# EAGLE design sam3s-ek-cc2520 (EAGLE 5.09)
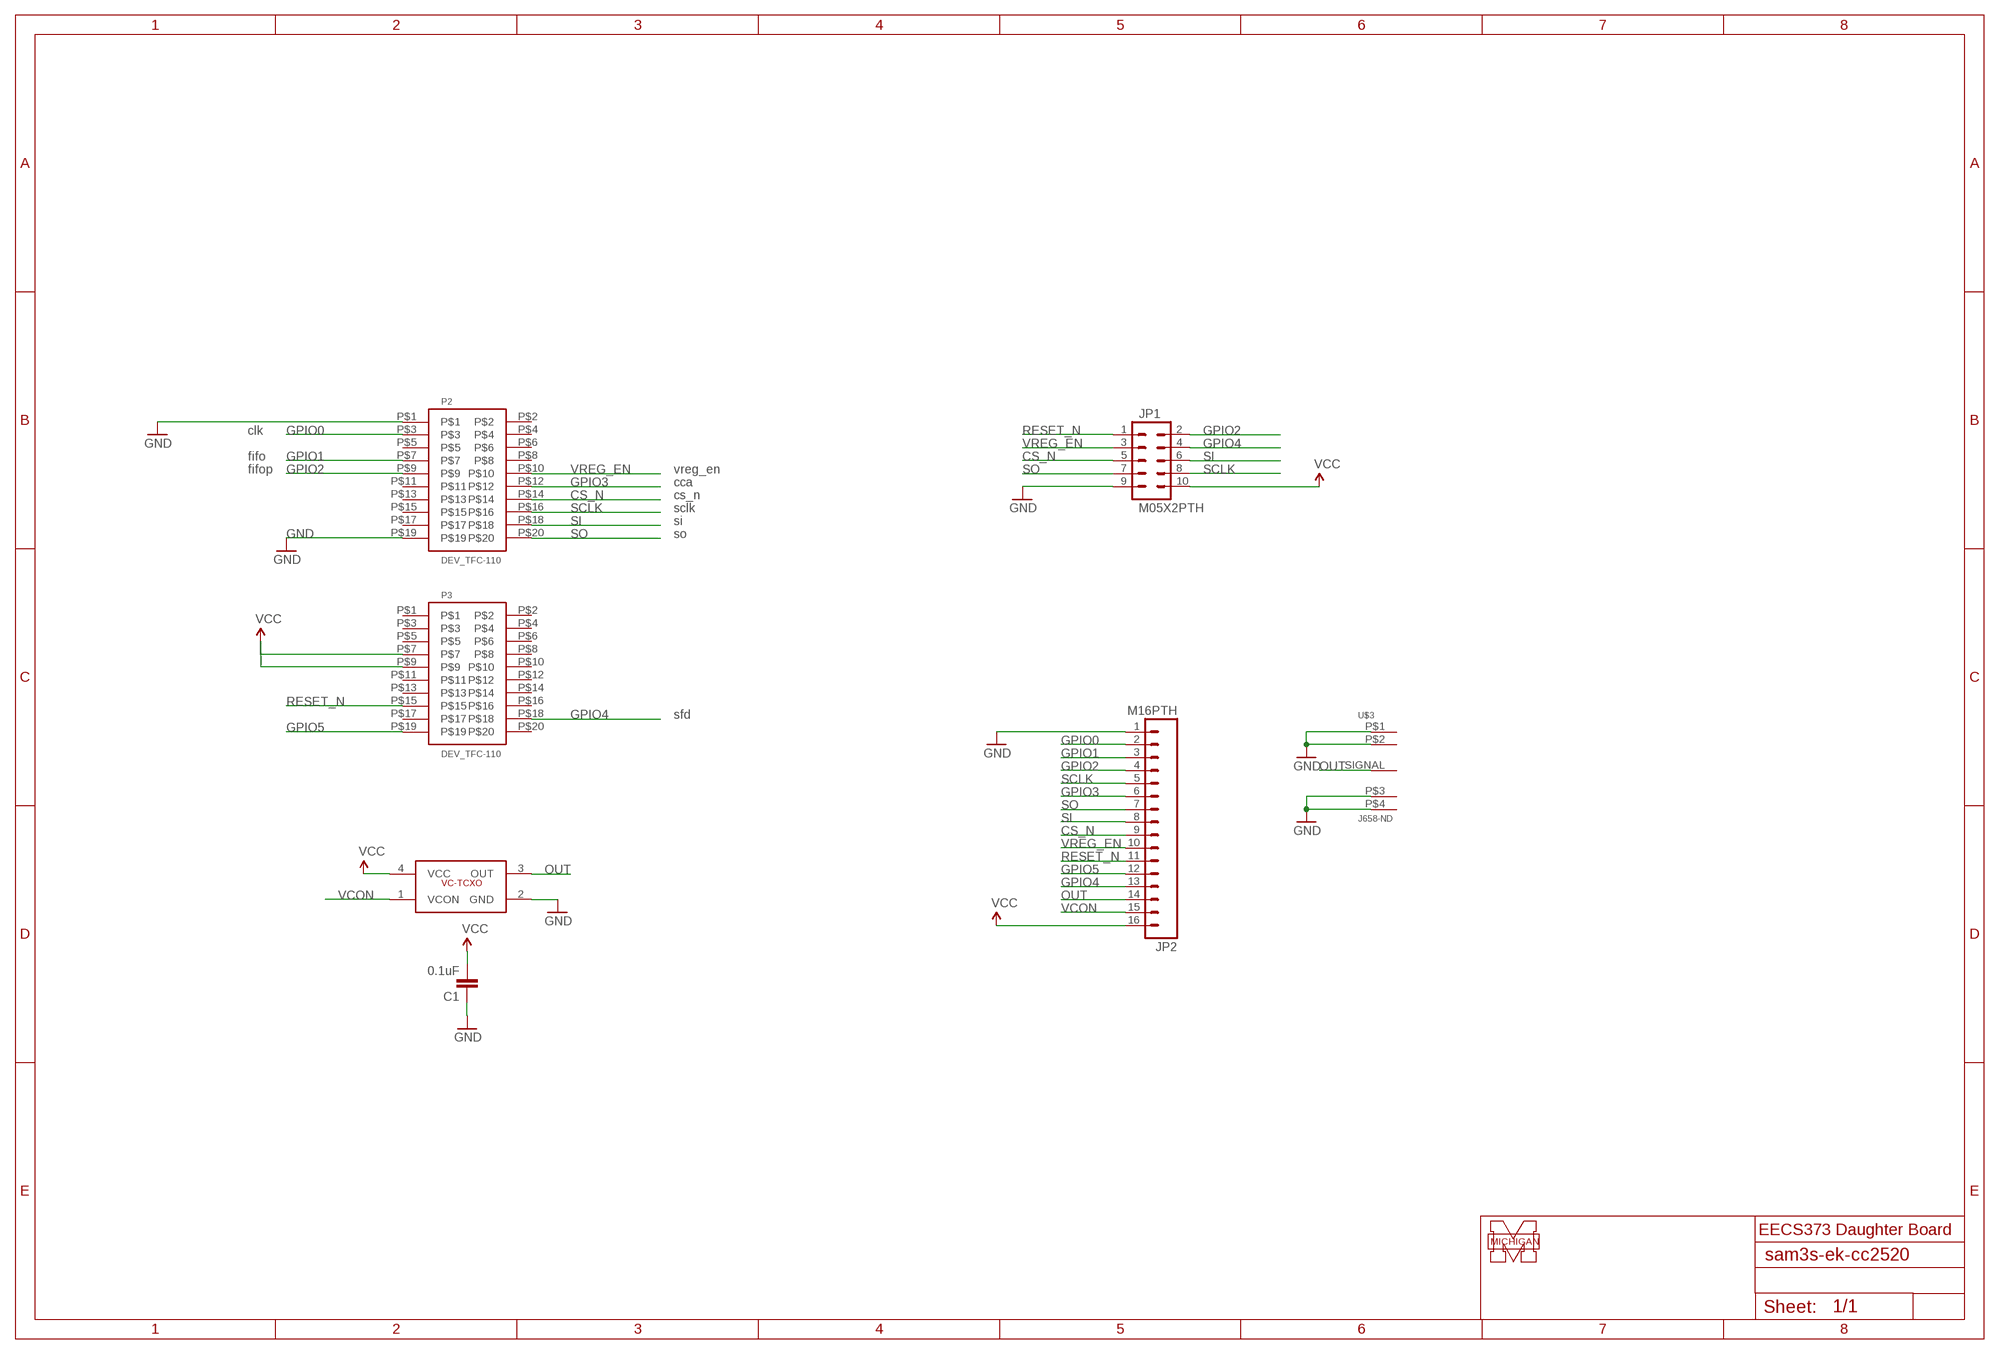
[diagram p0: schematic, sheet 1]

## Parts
C1  0.1uF  CAP0603-CAP  [0603-CAP]
JP1  M05X2PTH  [AVR_ICSP]
JP2  M16PTH  [1X16]
P2  DEV_TFC-110  [TFC-110]
P3  DEV_TFC-110  [TFC-110]
U$2  KT3225  [KT3225]
U$3  J658-ND  [SMA-SMD]

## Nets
CS_N: JP1.5 JP2.9 P2.P$14
GND: C1.1 JP1.9 JP2.1 P2.P$1 P2.P$19 U$2.2(GND) U$3.P$1(GND1) U$3.P$2(GND2) U$3.P$3(GND3) U$3.P$4(GND4)
GPIO0: JP2.2 P2.P$3
GPIO1: JP2.3 P2.P$7
GPIO2: JP1.2 JP2.4 P2.P$9
GPIO3: JP2.6 P2.P$12
GPIO4: JP1.4 JP2.13 P3.P$18
GPIO5: JP2.12 P3.P$19
OUT: JP2.14 U$2.3(OUT) U$3.SIGNAL
RESET_N: JP1.1 JP2.11 P3.P$15
SCLK: JP1.8 JP2.5 P2.P$16
SI: JP1.6 JP2.8 P2.P$18
SO: JP1.7 JP2.7 P2.P$20
VCC: C1.2 JP1.10 JP2.16 P3.P$7 P3.P$9 U$2.4(VCC)
VCON: JP2.15 U$2.1(VCON)
VREG_EN: JP1.3 JP2.10 P2.P$10
Unconnected: P2.P$2 P2.P$4 P2.P$5 P2.P$6 P2.P$8 P2.P$11 P2.P$13 P2.P$15 P2.P$17 P3.P$1 P3.P$2 P3.P$3 P3.P$4 P3.P$5 P3.P$6 P3.P$8 P3.P$10 P3.P$11 P3.P$12 P3.P$13 P3.P$14 P3.P$16 P3.P$17 P3.P$20

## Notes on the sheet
- clk
- fifo
- fifop | vreg_en
- cca
- cs_n
- sclk
- si
- so
- sfd
- EECS373 Daughter Board
- MICHIGAN

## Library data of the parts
C1 = SparkFun:CAP: Capacitor
JP1 = SparkFun:M05X2: Header 5x2 Standard 10-pin dual row 0.1" header. Commonly used with AVR-ISP. Use with Spark Fun Electronics SKU: PRT-00778
JP2 = SparkFun:M16
P2 P3 = EECS370:DEV_TFC-110
U$2 = utah:KT3225
U$3 = sam:J658-ND

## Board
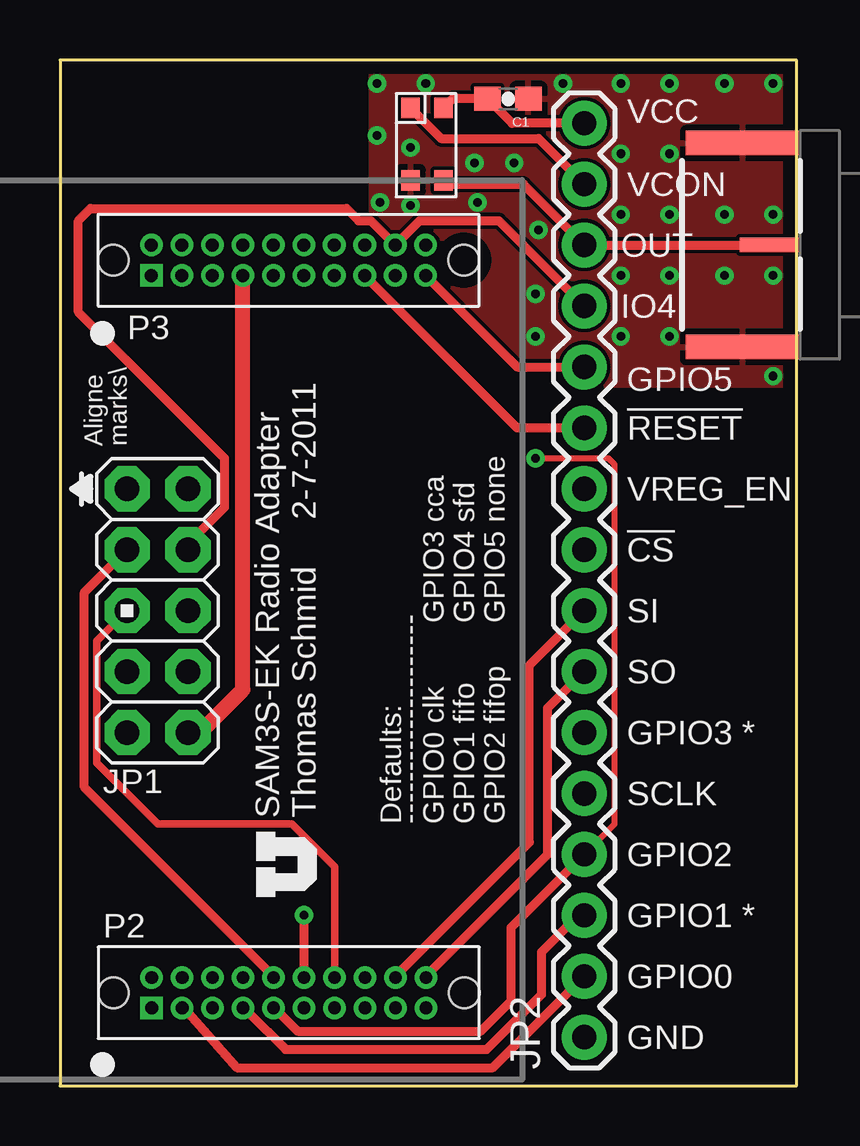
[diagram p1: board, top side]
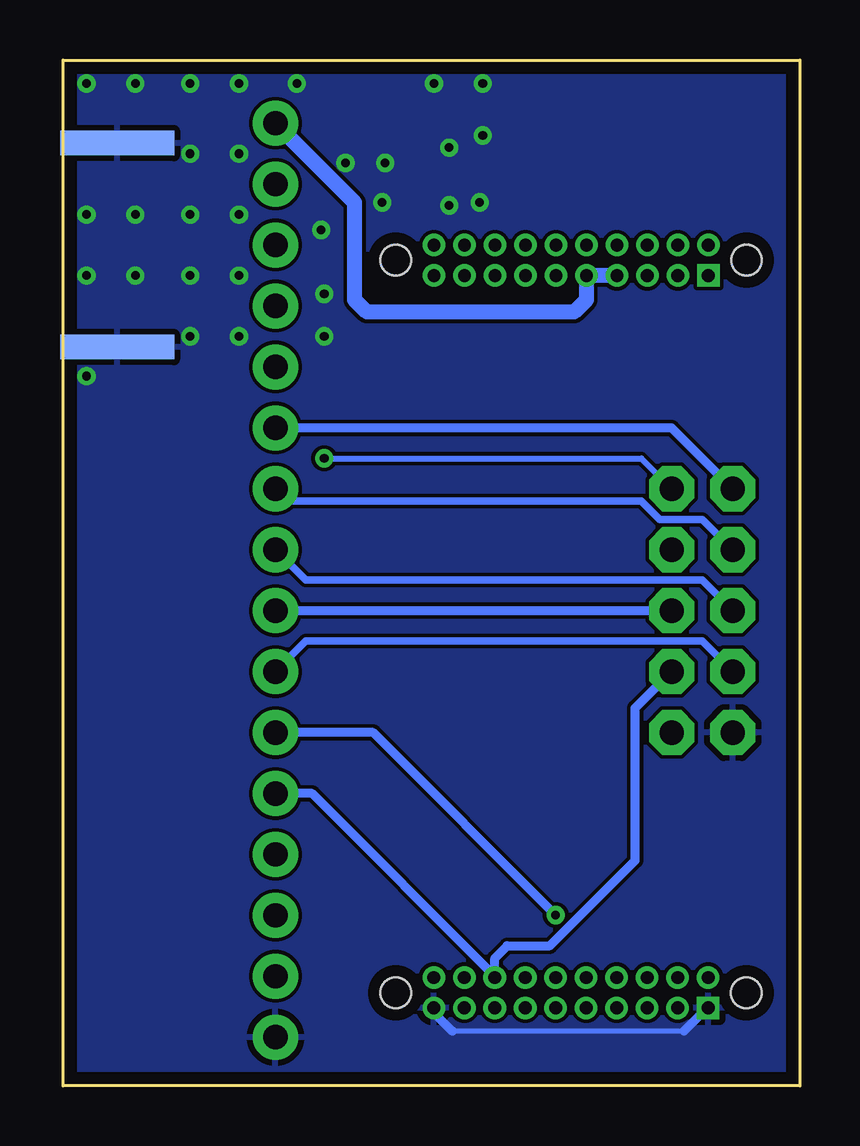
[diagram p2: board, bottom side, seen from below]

Size 30.69 x 42.77 mm. Coordinates in mm from the lower left corner, seen from the top.
Outline: 0,0 30.69,0 30.69,42.77 0,42.77 0,0
Copper layers (1*16): Top 0.0178mm / dielectric 1.4986mm / Bottom 0.0178mm
Design rules "SSC-EAGLE-2Lyr_v1.0.0.3 *": minimum track width 8mil, minimum drill 14mil, track to track 6mil, track to pad 6mil, pad to pad 6mil, via to via 6mil, smd to smd 6mil, copper to edge 20mil, drill to drill 16mil, minimum pad ring 8mil, minimum via ring 8mil, stop-mask expansion 3mil, vias tented up to drill 14mil, thermal gap 10mil

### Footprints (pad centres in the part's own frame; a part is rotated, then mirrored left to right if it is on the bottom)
0603-CAP = smd 1.1 x 1: 1 -0.85,0; 2 0.85,0
AVR_ICSP = drill 1.016 pad 1.88 octagon: 1 -1.27,5.08; 2 1.27,5.08; 3 -1.27,2.54; 4 1.27,2.54; 5 -1.27,0; 6 1.27,0; 7 -1.27,-2.54; 8 1.27,-2.54; 9 -1.27,-5.08; 10 1.27,-5.08
1X16 = drill 1.016 pad 1.88 round: 1 0,0; 2 2.54,0; 3 5.08,0; 4 7.62,0; 5 10.16,0; 6 12.7,0; 7 15.24,0; 8 17.78,0; 9 20.32,0; 10 22.86,0; 11 25.4,0; 12 27.94,0; 13 30.48,0; 14 33.02,0; 15 35.56,0; 16 38.1,0
TFC-110 = drill 0.533 square: P$1 -5.715,-0.635 | drill 0.533 round: P$2 -5.715,0.635; P$3 -4.445,-0.635; P$4 -4.445,0.635; P$5 -3.175,-0.635; P$6 -3.175,0.635; P$7 -1.905,-0.635; P$8 -1.905,0.635; P$9 -0.635,-0.635; P$10 -0.635,0.635; P$11 0.635,-0.635; P$12 0.635,0.635; P$13 1.905,-0.635; P$14 1.905,0.635; P$15 3.175,-0.635; P$16 3.175,0.635; P$17 4.445,-0.635; P$18 4.445,0.635; P$19 5.715,-0.635; P$20 5.715,0.635 | hole 1.27: 7.305,0; -7.305,0
KT3225 = smd 0.87 x 0.78: 1 0,0; 2 3.02,0; 3 3.02,1.37; 4 0,1.37
SMA-SMD = smd 1.02 x 4.75: P$1 -4.25,0; P$2 4.25,0 | smd 1.02 x 4.75 bottom: P$3 4.25,0; P$4 -4.25,0 | smd 0.6 x 2.5: SIGNAL 0,1.125

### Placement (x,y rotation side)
C1  18.67,41.15 180 top
JP1  4.06,19.81 0 top
JP2  21.84,2.03 90 top
P2  9.53,3.89 0 top
P3  9.52,34.42 0 top
U$1  [UTAH_LOGO]  10.67,7.87 90 top
U$2  14.61,40.77 270 top
U$3  28.45,35.05 270 top

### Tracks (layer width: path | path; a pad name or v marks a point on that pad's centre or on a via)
CS_N
  Top 0.305: JP1.5 1.52,18.54 1.52,13.46 4.06,10.92 9.65,10.92 11.44,9.14 P2.P$14
  Bottom 0.203: P2.P$14 11.43,4.57
  Bottom 0.305: JP1.5 4.06,21.08 20.57,21.08 JP2.9
GND  (via drill 0.36)
  Bottom 0.203: 4.83,2.29 14.48,2.29 | 4.06,3.05 P2.P$1
  Bottom 0.254: 15.24,3.05 P2.P$19
  Bottom 0.381: 4.83,2.29 4.06,3.05 | 14.48,2.29 15.24,3.05
  other vias: 13.33,36.83 14.61,36.7 17.4,36.83 19.94,35.69 18.92,38.48 17.27,38.48 14.61,39.12 13.21,39.62 13.21,41.78 15.24,41.78 20.96,41.78 23.37,41.78 25.4,41.78 25.4,38.86 23.37,38.86 23.37,36.32 25.4,36.32 23.37,33.78 25.4,33.78 27.69,33.78 29.72,33.78 29.72,36.32 27.69,36.32 27.69,41.78 29.72,41.78 29.72,29.59 25.4,31.24 23.37,31.24 19.81,33.02 19.81,31.24
  pour Bottom: 0.25,42.67 0.25,-0.51 30.48,-0.25 30.48,42.93
  pour Top: 12.95,42.67 12.95,29.21 30.23,29.21 30.23,42.67
GPIO0
  Top 0.381: P2.P$3 5.33,3.05 7.37,0.76 18.03,0.76 JP2.2
GPIO1
  Top 0.203: 21.59,7.11 JP2.3
  Top 0.381: P2.P$7 7.87,3.05 9.4,1.52 17.78,1.52 20.07,3.81 20.07,5.59 21.59,7.11
GPIO2  (via drill 0.36)
  Top 0.254: v19.81,26.16 22.86,26.16 23.11,25.91 23.11,10.92 JP2.4
  Top 0.381: P2.P$9 9.14,3.05 9.91,2.29 17.53,2.29 18.8,3.56 18.8,6.6 JP2.4
  Bottom 0.254: JP1.2 6.6,26.16 v19.81,26.16
GPIO3  (via drill 0.36)
  Top 0.381: P2.P$12 v10.17,7.12
  Bottom 0.381: v10.17,7.12 17.78,14.73 JP2.6
GPIO4
  Top 0.203: P3.P$18
  Top 0.381: P3.P$18 14.99,36.07 18.29,36.07 JP2.13 | JP1.4 5.33,22.61 6.86,24.13 6.86,26.16 0.76,32.26 0.76,36.07 1.27,36.58 11.94,36.58 12.45,36.07 12.95,36.07 P3.P$18
GPIO5
  Top 0.203: P3.P$19
  Top 0.381: P3.P$19 19.05,29.97 JP2.12
OUT
  Top 0.203: U$2.3 16.13,37.59
  Top 0.381: 16.13,37.59 19.3,37.59 JP2.14 U$3.SIGNAL
RESET_N
  Top 0.203: P3.P$15
  Top 0.381: P3.P$15 19.05,27.43 JP2.11
  Bottom 0.381: JP1.1 5.33,27.43 JP2.11
SCLK
  Bottom 0.203: P2.P$16 12.71,4.58
  Bottom 0.381: 12.71,4.58 20.32,12.19 JP2.5 | JP1.8 6.86,15.75 6.86,9.4 10.41,5.84 12.19,5.84 12.71,5.33 P2.P$16
SI
  Top 0.203: P2.P$18 13.97,4.57
  Top 0.381: 13.97,4.57 19.56,10.16 19.56,17.53 JP2.8
  Bottom 0.381: JP2.8 JP1.6
SO
  Top 0.203: P2.P$20 15.24,4.57
  Top 0.381: 15.24,4.57 20.32,9.65 20.32,15.75 JP2.7
  Bottom 0.305: JP1.7 4.06,18.54 20.57,18.54 JP2.7
VCC
  Top 0.381: U$2.4 16.36,41.15 C1.2 18.84,40.13 JP2.16
  Top 0.635: JP1.10 5.84,14.73 7.62,16.51 P3.P$7
  Bottom 0.635: P3.P$7 P3.P$9 8.89,32.77 9.4,32.26 18.03,32.26 18.54,32.77 18.54,36.83 JP2.16
VCON
  Top 0.381: U$2.1 15.88,39.5 19.94,39.5 JP2.15
VREG_EN
  Top 0.203: P2.P$10 8.89,4.57
  Top 0.381: 8.89,4.57 1.02,12.45 1.02,20.57 JP1.3
  Bottom 0.305: 21.34,24.38 6.6,24.38 5.84,23.62 4.06,23.62 JP1.3
  Bottom 0.381: 21.34,24.38 JP2.10

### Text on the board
tPlace: VCC | VCON | OUT | IO4 | GPIO5 | Aligne | marks\ | !RESET | 2-7-2011 | VREG_EN | !CS | GPIO3 cca | GPIO4 sfd | GPIO5 none | SI | SO | GPIO3 * | SCLK | SAM3S-EK Radio Adapter | Thomas Schmid | Defaults: | -------------------- | GPIO0 clk | GPIO1 fifo | GPIO2 fifop | GPIO2 | GPIO1 * | GPIO0 | GND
